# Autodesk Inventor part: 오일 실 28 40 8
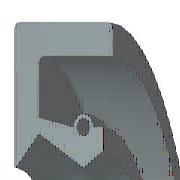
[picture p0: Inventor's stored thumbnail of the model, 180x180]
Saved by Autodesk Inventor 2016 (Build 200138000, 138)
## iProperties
IsCustomPart: 1
Created: 2012-02
Part Number: 오일 실 28 40 8
Material: 고무
Description: Oil-seal
Document SubType Name: Modeling
Standard: KS B 2804
Designer: mduedu
Standards Organization: KS
Language: en-US
Size Designation: D - 28 40 8
Categories: <MemberInstance><Categories><Category DisplayName="Shaft Parts" InternalName="7f7aeb1f-a693-4053-b835-cee3144e0d98" Mnemonic="SHFT"><Category DisplayName="Seali
Density: 0.93 g/cm^3
Mass: 2.83894 g
Surface Area: 40.7521 cm^2
Volume: 3.05262 cm^3
Appearance: 고무 - 검은색 - 버전 1.1
Author: mduedu
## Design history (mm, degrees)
sketch "Sketch1"
  geometry: L1 (0, 20)-(8, 20); L2 (8, 18.25)-(1.75, 18.25); L3 (1.75, 15.75)-(4.9, 14); L4 (4.9, 14)-(0, 14); L5 (0, 0)-(9.586, 0) reference; L6 (4.9, 14)-(6.3, 14.875); L7 (0, 18)-(0, -3) reference; L8 (-1.941, 0)-(11.507, 0) reference; L9 (4.2, 16.1)-(1.75, 16.71); L10 (1.75, 16.71)-(1.75, 18.25); L11 (0, 20)-(0, 14.088); L12 (4.9, 14)-(0, 14); L13 (1.75, 15.75)-(0.152, 14.028); L14 (8, 20)-(8, 18.25); L15 (5.6, 16.1)-(6.3, 16.1); L16 (6.3, 16.1)-(6.3, 14.875); C1 r 0.455 at (4.9, 16.1); A1 r 0.7 centre (4.9, 16.1) between (5.6, 16.1) and (4.2, 16.1); A2 r 0.088 centre (0.087, 14.088) between (0, 14.088) and (0.152, 14.028); 1 further point
  constraints: 28 end point, 5 horizontal alignment, 5 point on line, 4 point on circle, 4 vertical alignment, 3 centre point, 3 tangent, 2 collinear, 2 horizontal, 2 perpendicular, 1 coincident, 1 parallel
  dimensions: "d0" = 40 diameter of L1 L5 (= SD2); "d1" = 1.75 distance of L1.end L2.start (= SD); "d2" = 0.91 diameter of C1 (= SPDI); "d3" = 1.4 diameter of A1 (= SPDA); "d4" = 28 diameter of L3.end L5 (= NND); "d5" = 31.5 diameter of L3.start L5 (= TKDM); "d7" = 33.42 diameter of L9.end L5 (= TKDM + 0.24 x SWDT); "d8" = 1.75 distance between parallel lines of L11 L10 (= SD); "d9" = 4.9 distance from line of L11 C1.centre (= SPDST); "d10" = 32.2 diameter of C1.centre L5 (= HLDM); "d11" = 0.0875 radius of A2 (= 0.25 x LAB); "d12" = 6.3 distance between parallel lines of L11 L16 (= SDI); "d13" = 29.75 diameter of L6.end L5 (= ABDM); "d14" = 8 distance from line of L11 L1.end (= SWDT)
revolve "Body" stored, may be unused: angle "d17" = 90 deg
revolve "Spring1" stored, may be unused: angle "d18" = 90 deg
fillet "Fillet1" dims "d6" = 0.4 (= RR)
body "Solid1"
other parameters: "SD2" = 40 [user parameter; used in 1 equation term], "SWDT" = 8 [user parameter; used in 2 equation terms], "RR" = 0.4 [user parameter; used in 1 equation term], "SD" = 1.75 [user parameter; used in 2 equation terms], "NND" = 28 [user parameter; used in 1 equation term], "SPDA" = 1.4 [user parameter; used in 1 equation term], "SPDI" = 0.91 [user parameter; used in 1 equation term], "TKDM" = 31.5 [user parameter; used in 2 equation terms], "HLDM" = 32.2 [user parameter; used in 1 equation term], "ABDM" = 29.75 [user parameter; used in 1 equation term], "SDI" = 6.3 [user parameter; used in 1 equation term], "SPDST" = 4.9 [user parameter; used in 1 equation term], "LAB" = 0.35 [user parameter; used in 1 equation term], "d15" = 0, "d16" = 0, "d19" = 0
